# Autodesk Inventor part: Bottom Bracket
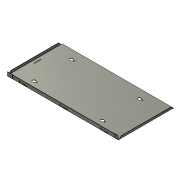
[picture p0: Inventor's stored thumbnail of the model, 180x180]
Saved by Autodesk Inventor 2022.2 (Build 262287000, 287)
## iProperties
Created: 2005-12
Material: アルミニウム 6061
Document SubType Name: Sheet Metal
Mass: 186.946 g
Surface Area: 1400.33 cm^2
Volume: 69.2392 cm^3
Density: 2.7 g/cm^3
Flat Pattern Width: 18.8178 cm
Flat Pattern Length: 37.2355 cm
Flat Pattern Area: 700.69 cm^2
Sheet Metal Rule: 1.0 mm
Sheet Metal Width: 188.178 mm
Sheet Metal Length: 372.355 mm
Sheet Metal Area: 70068.975 mm^2
Appearance: Silicon Nitride - Polished
SPACING: 261.036 mm
Author: Autodesk, Inc.
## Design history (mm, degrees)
node "Face1"
  sketch "Sketch2"
    geometry: L1 (0, 89)-(359, 89); L2 (0, -89)-(0, 89); L3 (359, -89)-(0, -89); L4 (359, 89)-(359, -89)
    constraints: 8 end point
node "Flange1"
sketch "Sketch4"
  geometry: L1 (359, 0)-(0, 0) reference; L2 (0, -178)-(359, -178) reference; L3 (359, -4.99)-(356.922, -4.99); L4 (356.922, -4.99)-(356.922, 0); L5 (356.922, 0)-(359, 0); L6 (359, 0)-(359, -4.99); L7 (359, -168.01)-(357.5, -168.01); L8 (357.5, -168.01)-(357.5, -178); L9 (357.5, -178)-(359, -178); L10 (359, -178)-(359, -168.01); L11 (357.5, -168)-(357.5, -5) reference
  constraints: 16 end point, 4 parallel, 2 horizontal, 2 perpendicular, 2 point on line, 1 collinear
cut "Cut1" sketch "Sketch4" dims "d11" = 1 (= Thickness), "d12" = 0
node "Flange2"
node "Flange3"
sketch "Sketch11"
  geometry: L1 (-18, -8.49)-(0, -8.49); L2 (0, -8.49)-(0, -10); L3 (0, -10)-(-18, -10); L4 (-18, -10)-(-18, -8.49)
  constraints: 8 end point, 2 parallel, 1 horizontal, 1 perpendicular
cut "Cut4" sketch "Sketch11" dims "d70" = 1 (= Thickness), "d71" = 0
node "Flange4"
node "Flange6"
sketch "Sketch9"
  geometry: L1 (-357.5, -5.01)-(-357.5, -10) reference; L2 (-18, -8.49)-(0, -8.49); L3 (0, -8.49)-(0, -10); L4 (0, -10)-(-18, -10); L5 (-18, -10)-(-18, -8.49); L6 (-347.51, -10)-(-357.5, -10); L7 (-357.5, -10)-(-357.5, -8.5); L8 (-357.5, -8.5)-(-347.51, -8.5); L9 (-347.51, -8.5)-(-347.51, -10); L10 (-347.5, -8.5)-(-345.768, -8.5) reference
  constraints: 16 end point, 4 parallel, 2 horizontal, 2 perpendicular, 1 point on line
cut "Cut2" sketch "Sketch9" dims "d49" = 1 (= Thickness), "d50" = 0
feature "Corner Chamfer1" dims "d51" = 5, "d52" = 6, angle "d53" = 45 deg
sketch "Sketch10"
  geometry: L1 (20, 5.5)-(32, 5.5); L2 (32, 5.5)-(32, 1.5); L3 (32, 1.5)-(20, 1.5); L4 (20, 1.5)-(20, 5.5); L5 (32, 5.5)-(37, 3); L6 (37, 3)-(45, 3); L7 (45, 3)-(45, 1.5); L8 (45, 1.5)-(32, 1.5); L9 (-21.232, 6.5)-(-21.232, 1.5) reference; L10 (0, 10.5)-(0, 0) reference
  constraints: 16 end point, 4 perpendicular, 2 parallel, 1 horizontal
  dimensions: "d57" = 4 distance of L3.end L1.start; "d58" = 1.5 distance of L6.end L7.end; "d59" = 25 distance between parallel lines of L4 L7; "d60" = 8 distance of L5.end L6.end; "d62" = 12 distance of L1.start L1.end; "d68" = 20 distance between parallel lines of L10 L4
cut "Cut3" sketch "Sketch10" dims "d63" = 1 (= Thickness), "d64" = 0
pattern_linear "Rectangular Pattern1" dims "SPACING" = 261.0359 (computed from d54)
sketch "Sketch12"
  geometry: L1 (-37.4, 79)-(465.2, 79); L2 (8.5, 89)-(11.5, 89); L3 (11.5, 89)-(11.5, 69); L4 (11.5, 69)-(8.5, 69); L5 (8.5, 69)-(8.5, 89); L6 (-1.5, -10)-(-1.5, 168); L7 (357.5, 168)-(357.5, -10); L8 (58.5, 20.5)-(68.5, 20.5); L9 (68.5, 20.5)-(68.5, 17.5); L10 (68.5, 17.5)-(58.5, 17.5); L11 (58.5, 17.5)-(58.5, 20.5); L12 (58.5, 140.5)-(68.5, 140.5); L13 (68.5, 140.5)-(68.5, 137.5); L14 (68.5, 137.5)-(58.5, 137.5); L15 (58.5, 137.5)-(58.5, 140.5); L16 (277.5, 140.5)-(287.5, 140.5); L17 (287.5, 140.5)-(287.5, 137.5); L18 (287.5, 137.5)-(277.5, 137.5); L19 (277.5, 137.5)-(277.5, 140.5); L20 (277.5, 20.5)-(287.5, 20.5); L21 (287.5, 20.5)-(287.5, 17.5); L22 (287.5, 17.5)-(277.5, 17.5); L23 (277.5, 17.5)-(277.5, 20.5); C1 r 5 at (58.5, 19); C2 r 5 at (277.5, 19); C3 r 5 at (58.5, 139); C4 r 5 at (277.5, 139); 4 further points
  constraints: 46 end point, 10 parallel, 6 equal length, 5 horizontal, 5 perpendicular, 4 centre point, 4 coincident, 4 midpoint, 3 equal radius, 2 horizontal alignment, 2 vertical alignment, 1 symmetric about line, 1 other
  dimensions: "d72" = 3 distance of L2.start L2.end; "d73" = 20 distance of L2.end L3.end; "d74" = 10 distance between parallel lines of L6 L5; "d75" = 60 distance from line of C1.centre L6; "d76" = 80 distance from line of L7 C2.centre; "d77" = 120 distance of C1.centre C3.centre; "d78" = 10 diameter of C1; "d79" = 10 distance of L8.start L8.end; "d80" = 3 distance of L8.end L9.end
cut "Cut5" sketch "Sketch12" dims "d81" = 1 (= Thickness), "d82" = 0
body "Solid1"
face "Plate1" dims "d93" = 1 (derived)
sketch "Sketch3"
  geometry: L1 (-5, 0)-(-168, 0); L2 (-168, 0)-(-168, 8); L3 (-168, 8)-(-5, 8); L4 (-5, 8)-(-5, 0)
  constraints: 8 end point
face "Plate2" dims "d2" = 10, "d3" = 5, "d6" = 2 (= MinimumRemnant), "d8" = 8, "d9" = 90 deg, "d10" = 0.5 (= BendRadius), "d93" = 1 (derived), "SeamGap" = 0.01
bend "Bend1" dims "d4" = 1 (= BendReliefWidth), "d5" = 0.5 (= BendReliefDepth), "d6" = 2 (= MinimumRemnant), "d7" = 0.5 (= BendRadius), "d8" = 8, "d9" = 90 deg, "d10" = 0.5 (= BendRadius), "d93" = 1 (derived), "SeamGap" = 0.01
sketch "Sketch5"
  geometry: L1 (-5, 0)-(-175, 0); L2 (-175, 0)-(-175, 8); L3 (-175, 8)-(-5, 8); L4 (-5, 8)-(-5, 0)
  constraints: 8 end point
face "Plate3" dims "d15" = 2 (= MinimumRemnant), "d17" = 8, "d18" = 90 deg, "d19" = 0.5 (= BendRadius), "d20" = 3, "d21" = 5, "d93" = 1 (derived), "SeamGap" = 0.01
bend "Bend2" dims "d13" = 1 (= BendReliefWidth), "d14" = 0.5 (= BendReliefDepth), "d15" = 2 (= MinimumRemnant), "d16" = 0.5 (= BendRadius), "d17" = 8, "d18" = 90 deg, "d19" = 0.5 (= BendRadius), "d93" = 1 (derived), "SeamGap" = 0.01
sketch "Sketch6"
  geometry: L1 (-18, 0)-(-347.5, 0); L2 (-347.5, 0)-(-347.5, 12); L3 (-347.5, 12)-(-18, 12); L4 (-18, 12)-(-18, 0)
  constraints: 8 end point
face "Plate4" dims "d22" = 10, "d23" = 18, "d26" = 2 (= MinimumRemnant), "d28" = 12, "d29" = 90 deg, "d30" = 0.5 (= BendRadius), "d93" = 1 (derived), "SeamGap" = 0.01
bend "Bend3" dims "d24" = 1 (= BendReliefWidth), "d25" = 0.5 (= BendReliefDepth), "d26" = 2 (= MinimumRemnant), "d27" = 0.5 (= BendRadius), "d28" = 12, "d29" = 90 deg, "d30" = 0.5 (= BendRadius), "d93" = 1 (derived), "SeamGap" = 0.01
sketch "Sketch7"
  geometry: L1 (0, -10.5)-(17, -10.5); L2 (17, -10.5)-(17, 0); 1 other entity
  constraints: 4 end point, 4 other
face "Plate5" dims "d33" = 2 (= MinimumRemnant), "d35" = 17, "d36" = 0, "d37" = 0.5 (= BendRadius), "d93" = 1 (derived), "SeamGap" = 0.01
bend "Bend4" dims "d31" = 1 (= BendReliefWidth), "d32" = 0.5 (= BendReliefDepth), "d33" = 2 (= MinimumRemnant), "d34" = 0.5 (= BendRadius), "d35" = 17, "d36" = 0, "d37" = 0.5 (= BendRadius), "d93" = 1 (derived), "SeamGap" = 0.01
sketch "Sketch13"
  geometry: L1 (-8.5, 0)-(-8.5, 10.5); L2 (-8.5, 10.5)-(0, 10.5); 1 other entity
  constraints: 4 end point, 4 other
face "Plate7" dims "d83" = 1 (derived), "d84" = 0.5 (derived), "d85" = 2 (derived), "d86" = 0.5 (derived), "d87" = 8.5, "d88" = 0, "d89" = 0.5 (derived), "d90" = 4 (derived), "d91" = 1 (derived), "d92" = 1 (derived), "d93" = 1 (derived), "SeamGap" = 0.01
bend "Bend6" dims "d83" = 1 (derived), "d84" = 0.5 (derived), "d85" = 2 (derived), "d86" = 0.5 (derived), "d87" = 8.5, "d88" = 0, "d89" = 0.5 (derived), "d93" = 1 (derived), "SeamGap" = 0.01
feature "Corner1" dims "d87" = 8.5, "d88" = 0, "d90" = 4 (derived), "d91" = 1 (derived), "d92" = 1 (derived)
feature "Definition1"
other parameters: "Thickness" = 1, "BendRadius" = 0.5 (derived), "BendReliefWidth" = 1 (derived), "BendReliefDepth" = 0.5 (derived), "CornerReliefSize" = 4 (derived), "MinimumRemnant" = 2 (derived), "TransitionRadius" = 0.5 (derived), "d1" = 0.5 (= BendRadius), "d54" = 326.0359 (derived), "JacobiRadiusSize" = 1 (derived), "GapSize" = 1 (derived), "BendRadius" = 0.5, "BendReliefDepth" = 0.5, "BendReliefWidth" = 1, "CornerReliefSize" = 4, "JacobiRadiusSize" = 1, "MinimumRemnant" = 2, "SPACING" = 261.0359, "Thickness" = 1, "TransitionRadius" = 0.5, "GapSize" = 1
